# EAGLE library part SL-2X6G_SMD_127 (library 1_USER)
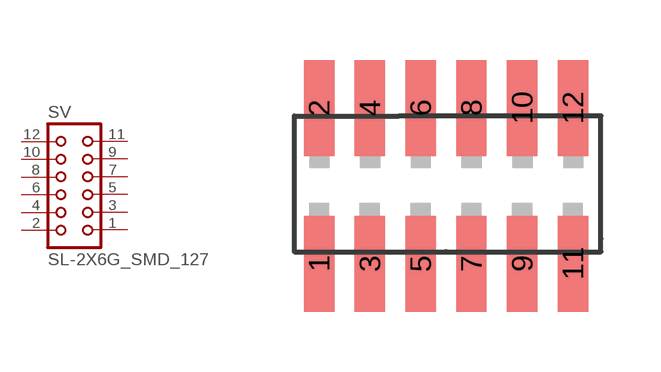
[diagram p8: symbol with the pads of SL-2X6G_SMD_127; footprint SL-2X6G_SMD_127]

Designator prefix SV

## SL-2X6G_SMD_127  [SL-2X6G_SMD_127]
1  1  pas
2  2  pas
3  3  pas
4  4  pas
5  5  pas
6  6  pas
7  7  pas
8  8  pas
9  9  pas
10  10  pas
11  11  pas
12  12  pas

## Footprint SL-2X6G_SMD_127 (pad centres in mm)
smd 0.76 x 2.4: 1 0.12,-1.9; 2 0.12,2; 3 1.39,-1.9; 4 1.39,2; 5 2.66,-1.9; 6 2.66,2; 7 3.93,-1.9; 8 3.93,2; 9 5.2,-1.9; 10 5.2,2; 11 6.47,-1.9; 12 6.47,2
